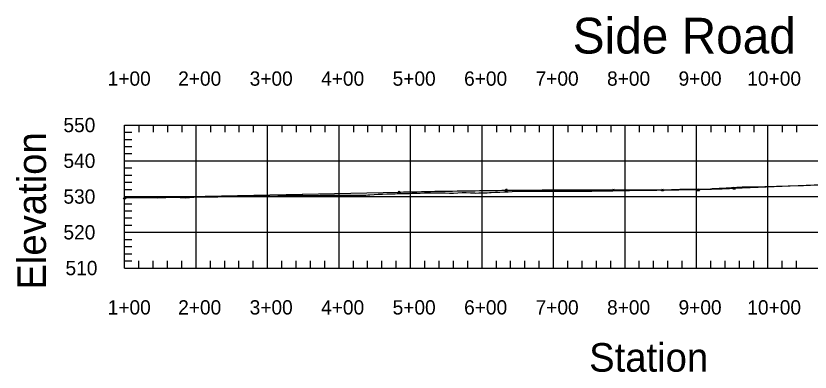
# Model space of a CAD drawing. Extents: x 704797 to 712284, y 374940 to 376945.
# Drawn here: x 708267 to 709378, y 376447 to 376945 of the extents above; entities that cross this region are included whole.
import ezdxf

# ---------------------------------------------------------------- set-up
doc = ezdxf.new("R2010")
doc.units = 0
for name, color, linetype in [('1', 7, 'Continuous'), ('48', 7, 'Continuous'), ('61', 7, 'Continuous'), ('Existing', 7, 'Continuous')]:
    doc.layers.add(name, color=color, linetype=linetype)

msp = doc.modelspace()

# ---------------------------------------------------------------- linework, layer by layer
for points in [[(708803.4, 376700.1), (708804.9, 376697.1), (708801.9, 376697.1)], [(708953.4, 376703.3), (708954.9, 376700.3), (708951.9, 376700.3)], [(709103.4, 376703.3), (709104.9, 376700.3), (709101.9, 376700.3)], [(709172, 376703.3), (709173.5, 376700.3), (709170.5, 376700.3)], [(709222, 376703.3), (709223.5, 376700.3), (709220.5, 376700.3)], [(709272, 376705.4), (709273.5, 376702.4), (709270.5, 376702.4)], [(708419.5, 376691.9), (708421, 376688.9), (708418, 376688.9)]]:
    msp.add_lwpolyline(points, close=True)
at = {"layer": '48'}
for p, q in [((709272, 376703.9), (709395.4, 376709.2)), ((708419.5, 376690.4), (708803.4, 376698.6)), ((709103.4, 376701.8), (709172, 376701.8))]:
    msp.add_line(p, q, dxfattribs=at)
for points in [[(708803.4, 376698.6), (708809.7, 376698.7), (708815.9, 376698.9), (708822.2, 376699), (708828.4, 376699.1), (708834.7, 376699.2), (708840.9, 376699.4), (708847.2, 376699.5), (708853.4, 376699.6), (708859.7, 376699.7), (708865.9, 376699.8), (708872.2, 376699.9), (708878.4, 376700), (708884.7, 376700.1), (708890.9, 376700.2), (708897.2, 376700.3), (708903.4, 376700.4), (708909.7, 376700.5), (708915.9, 376700.6), (708922.2, 376700.7), (708928.4, 376700.7), (708934.7, 376700.8), (708940.9, 376700.9), (708947.2, 376701), (708959.7, 376701.1), (708965.9, 376701.1), (708972.2, 376701.2), (708978.4, 376701.3), (708984.7, 376701.3), (708990.9, 376701.4), (708997.2, 376701.4), (709003.4, 376701.5), (709009.7, 376701.5), (709015.9, 376701.6), (709022.2, 376701.6), (709028.4, 376701.6), (709034.7, 376701.7), (709040.9, 376701.7), (709047.2, 376701.7), (709053.4, 376701.7), (709059.7, 376701.8), (709065.9, 376701.8), (709072.2, 376701.8), (709078.4, 376701.8), (709084.7, 376701.8), (709090.9, 376701.8), (709097.2, 376701.8), (709103.4, 376701.8)], [(709172, 376701.8), (709174, 376701.8), (709176.1, 376701.8), (709178.2, 376701.8), (709180.3, 376701.8), (709182.4, 376701.8), (709184.5, 376701.9), (709186.5, 376701.9), (709188.6, 376701.9), (709190.7, 376701.9), (709192.8, 376701.9), (709194.9, 376701.9), (709197, 376702), (709199, 376702), (709201.1, 376702), (709203.2, 376702), (709205.3, 376702.1), (709207.4, 376702.1), (709209.5, 376702.1), (709211.5, 376702.2), (709213.6, 376702.2), (709215.7, 376702.2), (709217.8, 376702.3), (709219.9, 376702.3), (709224, 376702.4), (709226.1, 376702.4), (709228.2, 376702.5), (709230.3, 376702.5), (709232.4, 376702.6), (709234.5, 376702.7), (709236.5, 376702.7), (709238.6, 376702.8), (709240.7, 376702.8), (709242.8, 376702.9), (709244.9, 376702.9), (709247, 376703), (709249, 376703.1), (709251.1, 376703.1), (709253.2, 376703.2), (709255.3, 376703.3), (709257.4, 376703.4), (709259.5, 376703.4), (709261.5, 376703.5), (709263.6, 376703.6), (709265.7, 376703.7), (709267.8, 376703.8), (709269.9, 376703.9), (709272, 376703.9)]]:
    msp.add_lwpolyline(points, dxfattribs=at)
at = {"layer": '61'}
for p, q in [((708419.5, 376792.3), (709919.5, 376792.3)), ((708419.5, 376592.3), (708419.5, 376792.3)), ((708439.5, 376792.3), (708439.5, 376782.3)), ((708459.5, 376792.3), (708459.5, 376782.3)), ((708479.5, 376792.3), (708479.5, 376782.3)), ((708499.5, 376792.3), (708499.5, 376782.3)), ((708519.5, 376592.3), (708519.5, 376792.3)), ((708539.5, 376792.3), (708539.5, 376782.3)), ((708559.5, 376792.3), (708559.5, 376782.3)), ((708579.5, 376792.3), (708579.5, 376782.3)), ((708599.5, 376792.3), (708599.5, 376782.3)), ((708619.5, 376592.3), (708619.5, 376792.3)), ((708639.5, 376792.3), (708639.5, 376782.3)), ((708659.5, 376792.3), (708659.5, 376782.3)), ((708679.5, 376792.3), (708679.5, 376782.3)), ((708699.5, 376792.3), (708699.5, 376782.3)), ((708719.5, 376592.3), (708719.5, 376792.3)), ((708739.5, 376792.3), (708739.5, 376782.3)), ((708759.5, 376792.3), (708759.5, 376782.3)), ((708779.5, 376792.3), (708779.5, 376782.3)), ((708799.5, 376792.3), (708799.5, 376782.3)), ((708819.5, 376592.3), (708819.5, 376792.3)), ((708839.5, 376792.3), (708839.5, 376782.3)), ((708859.5, 376792.3), (708859.5, 376782.3)), ((708879.5, 376792.3), (708879.5, 376782.3)), ((708899.5, 376792.3), (708899.5, 376782.3)), ((708919.5, 376592.3), (708919.5, 376792.3)), ((708939.5, 376792.3), (708939.5, 376782.3)), ((708959.5, 376792.3), (708959.5, 376782.3)), ((708979.5, 376792.3), (708979.5, 376782.3)), ((708999.5, 376792.3), (708999.5, 376782.3)), ((709019.5, 376592.3), (709019.5, 376792.3)), ((709039.5, 376792.3), (709039.5, 376782.3)), ((709059.5, 376792.3), (709059.5, 376782.3)), ((709079.5, 376792.3), (709079.5, 376782.3)), ((709099.5, 376792.3), (709099.5, 376782.3)), ((709119.5, 376592.3), (709119.5, 376792.3)), ((709139.5, 376792.3), (709139.5, 376782.3)), ((709159.5, 376792.3), (709159.5, 376782.3)), ((709179.5, 376792.3), (709179.5, 376782.3)), ((709199.5, 376792.3), (709199.5, 376782.3)), ((709219.5, 376592.3), (709219.5, 376792.3)), ((709239.5, 376792.3), (709239.5, 376782.3)), ((709259.5, 376792.3), (709259.5, 376782.3)), ((709279.5, 376792.3), (709279.5, 376782.3)), ((709299.5, 376792.3), (709299.5, 376782.3)), ((709319.5, 376592.3), (709319.5, 376792.3)), ((709339.5, 376792.3), (709339.5, 376782.3)), ((709359.5, 376792.3), (709359.5, 376782.3)), ((708419.5, 376782.3), (708429.5, 376782.3)), ((708419.5, 376772.3), (708429.5, 376772.3)), ((708419.5, 376762.3), (708429.5, 376762.3)), ((708419.5, 376752.3), (708429.5, 376752.3)), ((708419.5, 376742.3), (709919.5, 376742.3)), ((708419.5, 376732.3), (708429.5, 376732.3)), ((708419.5, 376722.3), (708429.5, 376722.3)), ((708419.5, 376712.3), (708429.5, 376712.3)), ((708419.5, 376702.3), (708429.5, 376702.3)), ((708419.5, 376692.3), (709919.5, 376692.3)), ((708419.5, 376682.3), (708429.5, 376682.3)), ((708419.5, 376672.3), (708429.5, 376672.3)), ((708419.5, 376662.3), (708429.5, 376662.3)), ((708419.5, 376652.3), (708429.5, 376652.3)), ((708419.5, 376642.3), (709919.5, 376642.3)), ((708419.5, 376632.3), (708429.5, 376632.3)), ((708419.5, 376622.3), (708429.5, 376622.3)), ((708419.5, 376612.3), (708429.5, 376612.3)), ((708419.5, 376602.3), (708429.5, 376602.3)), ((708439.5, 376592.3), (708439.5, 376602.3)), ((708459.5, 376592.3), (708459.5, 376602.3)), ((708479.5, 376592.3), (708479.5, 376602.3)), ((708499.5, 376592.3), (708499.5, 376602.3)), ((708539.5, 376592.3), (708539.5, 376602.3)), ((708559.5, 376592.3), (708559.5, 376602.3)), ((708579.5, 376592.3), (708579.5, 376602.3)), ((708599.5, 376592.3), (708599.5, 376602.3)), ((708639.5, 376592.3), (708639.5, 376602.3)), ((708659.5, 376592.3), (708659.5, 376602.3)), ((708679.5, 376592.3), (708679.5, 376602.3)), ((708699.5, 376592.3), (708699.5, 376602.3)), ((708739.5, 376592.3), (708739.5, 376602.3)), ((708759.5, 376592.3), (708759.5, 376602.3)), ((708779.5, 376592.3), (708779.5, 376602.3)), ((708799.5, 376592.3), (708799.5, 376602.3)), ((708839.5, 376592.3), (708839.5, 376602.3)), ((708859.5, 376592.3), (708859.5, 376602.3)), ((708879.5, 376592.3), (708879.5, 376602.3)), ((708899.5, 376592.3), (708899.5, 376602.3)), ((708939.5, 376592.3), (708939.5, 376602.3)), ((708959.5, 376592.3), (708959.5, 376602.3)), ((708979.5, 376592.3), (708979.5, 376602.3)), ((708999.5, 376592.3), (708999.5, 376602.3)), ((709039.5, 376592.3), (709039.5, 376602.3)), ((709059.5, 376592.3), (709059.5, 376602.3)), ((709079.5, 376592.3), (709079.5, 376602.3)), ((709099.5, 376592.3), (709099.5, 376602.3)), ((709139.5, 376592.3), (709139.5, 376602.3)), ((709159.5, 376592.3), (709159.5, 376602.3)), ((709179.5, 376592.3), (709179.5, 376602.3)), ((709199.5, 376592.3), (709199.5, 376602.3)), ((709239.5, 376592.3), (709239.5, 376602.3)), ((709259.5, 376592.3), (709259.5, 376602.3)), ((709279.5, 376592.3), (709279.5, 376602.3)), ((709299.5, 376592.3), (709299.5, 376602.3)), ((709339.5, 376592.3), (709339.5, 376602.3)), ((709359.5, 376592.3), (709359.5, 376602.3)), ((708419.5, 376592.3), (709919.5, 376592.3))]:
    msp.add_line(p, q, dxfattribs=at)
at = {"layer": 'Existing'}
msp.add_lwpolyline([(708419.5, 376690.4), (708452.7, 376690.9), (708452.7, 376690.9), (708466, 376690.4), (708488.6, 376691.6), (708489.7, 376691.6), (708504.1, 376690.5), (708522.5, 376691.8), (708523, 376691.8), (708549.8, 376691.8), (708561.5, 376692.8), (708600, 376693.4), (708614.2, 376692.8), (708623.2, 376693), (708644.7, 376693.6), (708648.3, 376693.8), (708651.3, 376693.8), (708663.1, 376694), (708663.2, 376694), (708669, 376694), (708674.8, 376693.9), (708680.4, 376693.9), (708680.7, 376693.9), (708682.8, 376693.8), (708684.3, 376693.8), (708685.8, 376693.8), (708686.5, 376693.8), (708692.4, 376694), (708698.2, 376694.1), (708704.1, 376694.3), (708706.5, 376694.3), (708710, 376694.3), (708715.6, 376694.2), (708715.8, 376694.2), (708721.7, 376694.3), (708726.2, 376694.4), (708727.5, 376694.4), (708727.6, 376694.4), (708729, 376694.4), (708730.4, 376694.4), (708733.4, 376694.4), (708739.2, 376694.3), (708745.1, 376694.2), (708750.9, 376694.2), (708751, 376694.2), (708754.8, 376694.3), (708756.8, 376694.4), (708759.6, 376694.5), (708762.7, 376694.7), (708768.5, 376695.1), (708774.4, 376695.5), (708775.1, 376695.6), (708775.3, 376695.6), (708776.9, 376695.6), (708780.2, 376695.8), (708786.1, 376695.9), (708791.9, 376696.1), (708793.5, 376696.1), (708797.8, 376696.3), (708803.7, 376696.4), (708809.5, 376696.6), (708814.4, 376696.7), (708815.4, 376696.7), (708815.5, 376696.7), (708816.6, 376696.7), (708817.5, 376696.7), (708821.2, 376696.9), (708827.1, 376697), (708832.9, 376697.2), (708838.8, 376697.4), (708843.4, 376697.5), (708844.7, 376697.5), (708850.5, 376697.6), (708851.2, 376697.6), (708851.7, 376697.6), (708856.4, 376697.6), (708862.2, 376697.4), (708868.1, 376697.3), (708873.9, 376697.2), (708878.9, 376697.1), (708879.8, 376697.1), (708885.7, 376697.6), (708891.5, 376698.1), (708892.1, 376698.1), (708892.4, 376698.1), (708892.6, 376698.1), (708892.9, 376698.1), (708897.4, 376697.9), (708903.2, 376697.6), (708909.1, 376697.3), (708909.7, 376697.2), (708914.9, 376697.3), (708915.3, 376697.4), (708920.4, 376697.5), (708920.8, 376697.5), (708925.4, 376697.7), (708926.7, 376697.7), (708930.1, 376697.8), (708932.5, 376697.9), (708938.4, 376698.2), (708944.2, 376698.5), (708950.1, 376698.8), (708955.9, 376699), (708961.8, 376699.3), (708967.7, 376699.6), (708969.1, 376699.6), (708972.6, 376699.7), (708973.5, 376699.8), (708975.1, 376699.8), (708979.4, 376699.9), (708983.4, 376700), (708985.2, 376700), (708988.5, 376700), (708991.1, 376700), (708996.9, 376700), (709002.8, 376700), (709008.6, 376700), (709014.5, 376700), (709016.8, 376700), (709020.4, 376700), (709026.2, 376699.9), (709026.5, 376699.9), (709032.1, 376700), (709033.1, 376700), (709034, 376700), (709034.9, 376700), (709035.8, 376700), (709037.9, 376700), (709043.8, 376700), (709046.4, 376699.9), (709049.6, 376699.9), (709051.3, 376699.8), (709055.5, 376699.9), (709056.5, 376699.9), (709061.4, 376699.8), (709066, 376699.7), (709067.2, 376699.7), (709067.2, 376699.7), (709068.5, 376699.7), (709073.1, 376699.9), (709078.9, 376700.1), (709080.8, 376700.1), (709084.8, 376700.2), (709085.7, 376700.2), (709090.6, 376700.2), (709093.6, 376700.3), (709096.5, 376700.3), (709098.2, 376700.3), (709102.4, 376700.4), (709108.2, 376700.6), (709114.1, 376700.8), (709115, 376700.8), (709116.2, 376700.8), (709117, 376700.8), (709117.8, 376700.8), (709119.9, 376700.9), (709125.8, 376700.9), (709128.9, 376701), (709131.6, 376701), (709137.5, 376701.1), (709137.7, 376701.2), (709143.4, 376701.3), (709146.9, 376701.4), (709149.2, 376701.4), (709155.1, 376701.4), (709160.8, 376701.4), (709160.9, 376701.4), (709162.3, 376701.4), (709164, 376701.4), (709166.8, 376701.5), (709172.6, 376701.7), (709178.4, 376701.9), (709178.5, 376701.9), (709184.4, 376702), (709185.2, 376702), (709190.2, 376702.1), (709191.6, 376702.1), (709196.1, 376702.4), (709201.5, 376702.7), (709201.6, 376702.7), (709201.7, 376702.7), (709212.1, 376702.6), (709219.3, 376702.8), (709239.3, 376703.3), (709241.2, 376703.4), (709261.1, 376704.4), (709283.6, 376706), (709297.9, 376706), (709315, 376706.3), (709347.9, 376707.4), (709348.1, 376707.4), (709348.3, 376707.4), (709369.1, 376707.8), (709399.2, 376708.9)], dxfattribs=at)

# ---------------------------------------------------------------- texts
at = {"layer": '1'}
for s, height, p in [('Side Road', 50, (709046.3, 376892.3)), ('Station', 40, (709069.3, 376447.3))]:
    msp.add_text(s, height=height, dxfattribs=at).set_placement(p)
msp.add_text('Elevation', height=40, rotation=90, dxfattribs=at).set_placement((708309.5, 376562.1))
at = {"layer": '61'}
for s, p in [('1+00', (708395.8, 376847.3)), ('2+00', (708494.4, 376847.3)), ('3+00', (708594.4, 376847.3)), ('4+00', (708694.4, 376847.3)), ('5+00', (708794.4, 376847.3)), ('6+00', (708894.4, 376847.3)), ('7+00', (708994.4, 376847.3)), ('8+00', (709094.4, 376847.3)), ('9+00', (709194.4, 376847.3)), ('10+00', (709290.6, 376847.3)), ('550', (708333.9, 376782.3)), ('550', (708333.9, 376782.3)), ('540', (708333.9, 376732.3)), ('530', (708333.9, 376682.3)), ('520', (708333.9, 376632.3)), ('510', (708336.8, 376582.3)), ('1+00', (708395.8, 376527.3)), ('2+00', (708494.4, 376527.3)), ('3+00', (708594.4, 376527.3)), ('4+00', (708694.4, 376527.3)), ('5+00', (708794.4, 376527.3)), ('6+00', (708894.4, 376527.3)), ('7+00', (708994.4, 376527.3)), ('8+00', (709094.4, 376527.3)), ('9+00', (709194.4, 376527.3)), ('10+00', (709290.6, 376527.3))]:
    msp.add_text(s, height=20, dxfattribs=at).set_placement(p)

doc.saveas('drawing.dxf')
